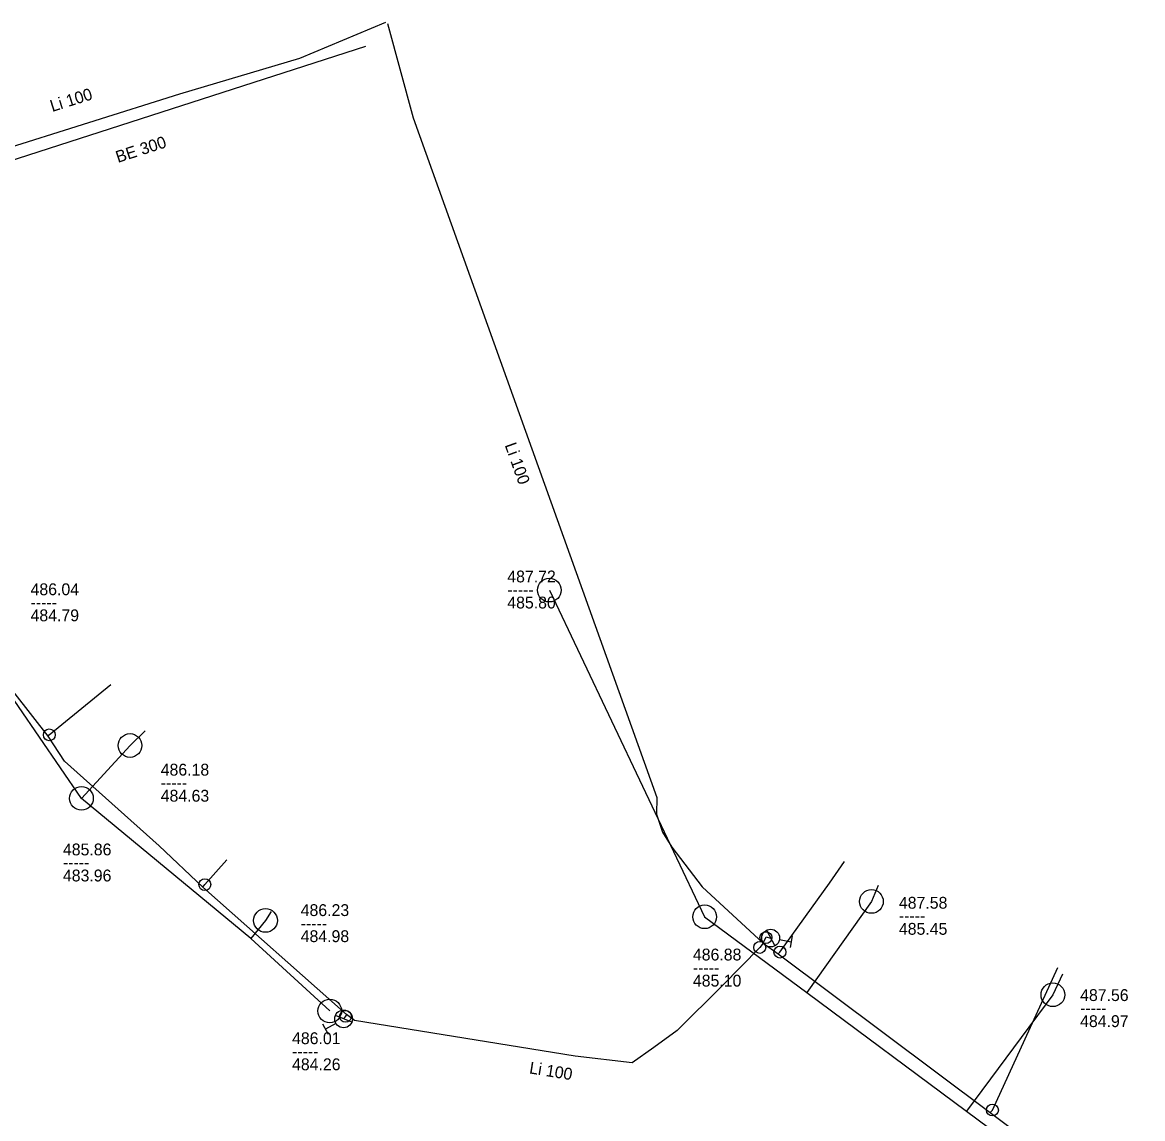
# Model space of a CAD drawing. Extents: x -685576 to -685145, y -1163436 to -1162895.
# Drawn here: x -685302.8 to -685208.3, y -1163269 to -1163176.5 of the extents above; entities that cross this region are included whole.
import ezdxf

# ---------------------------------------------------------------- set-up
doc = ezdxf.new("R2010")
doc.units = 0
doc.layers.add('Level 0', color=7, linetype='Continuous')

msp = doc.modelspace()

# ---------------------------------------------------------------- linework, layer by layer
at = {"layer": 'Level 0'}
for p, q in [((-685272.2, -1163176.49), (-685279.46, -1163179.53)), ((-685272.03, -1163176.58), (-685269.88, -1163184.54)), ((-685273.88, -1163178.51), (-685315.45, -1163191.93)), ((-685279.46, -1163179.53), (-685289.58, -1163182.54)), ((-685289.58, -1163182.54), (-685314.18, -1163190.28)), ((-685269.88, -1163184.54), (-685249.32, -1163241.89)), ((-685258.38, -1163224.39), (-685245.28, -1163251.95)), ((-685297.86, -1163241.96), (-685309.45, -1163225.05)), ((-685300.66, -1163236.72), (-685309.3, -1163225.68)), ((-685300.57, -1163236.6), (-685295.39, -1163232.34)), ((-685300.66, -1163236.72), (-685300.57, -1163236.6)), ((-685299.28, -1163238.81), (-685300.66, -1163236.72)), ((-685292.49, -1163236.25), (-685293.76, -1163237.5)), ((-685293.76, -1163237.5), (-685297.86, -1163241.96)), ((-685291.29, -1163245.96), (-685299.28, -1163238.81)), ((-685283.57, -1163253.78), (-685297.86, -1163241.96)), ((-685249.32, -1163241.89), (-685249.35, -1163243.29)), ((-685249.35, -1163243.29), (-685248.84, -1163244.81)), ((-685248.84, -1163244.81), (-685248.06, -1163246.08)), ((-685287.62, -1163249.46), (-685291.29, -1163245.96)), ((-685248.06, -1163246.08), (-685245.49, -1163249.43)), ((-685287.45, -1163249.24), (-685285.59, -1163247.15)), ((-685234.74, -1163249.11), (-685233.49, -1163247.28)), ((-685287.62, -1163249.46), (-685287.45, -1163249.24)), ((-685238.93, -1163254.93), (-685234.74, -1163249.11)), ((-685230.63, -1163249.31), (-685231.21, -1163250.66)), ((-685275.49, -1163260.19), (-685287.62, -1163249.46)), ((-685245.49, -1163249.43), (-685240.34, -1163254.18)), ((-685231.21, -1163250.66), (-685236.66, -1163258.35)), ((-685281.86, -1163251.51), (-685282.33, -1163252.26)), ((-685245.28, -1163251.95), (-685236.66, -1163258.35)), ((-685282.33, -1163252.26), (-685283.57, -1163253.78)), ((-685240.063, -1163253.091), (-685239.356, -1163254.414)), ((-685276.91, -1163259.9), (-685283.57, -1163253.78)), ((-685240.34, -1163254.18), (-685240.11, -1163253.71)), ((-685240.11, -1163253.71), (-685240.08, -1163253.63)), ((-685240.08, -1163253.63), (-685239.71, -1163253.75)), ((-685238.971, -1163253.88), (-685237.987, -1163254.054)), ((-685237.9, -1163253.561), (-685238.073, -1163254.546)), ((-685240.63, -1163254.54), (-685243.77, -1163257.74)), ((-685240.34, -1163254.18), (-685240.63, -1163254.54)), ((-685240.34, -1163254.18), (-685239.09, -1163255.09)), ((-685239.09, -1163255.09), (-685238.93, -1163254.93)), ((-685239.09, -1163255.09), (-685221.2, -1163268.46)), ((-685221, -1163268.26), (-685215.47, -1163256.23)), ((-685215.1, -1163256.8), (-685215.9, -1163258.53)), ((-685243.77, -1163257.74), (-685247.6, -1163261.56)), ((-685236.66, -1163258.35), (-685223.18, -1163268.34)), ((-685215.9, -1163258.53), (-685223.18, -1163268.34)), ((-685275.046, -1163260.848), (-685276.438, -1163260.289)), ((-685275.58, -1163260.35), (-685275.74, -1163260.57)), ((-685275.49, -1163260.19), (-685275.58, -1163260.35)), ((-685274.82, -1163260.69), (-685275.49, -1163260.19)), ((-685256.19, -1163263.72), (-685274.82, -1163260.69)), ((-685277.006, -1163261.878), (-685277.506, -1163261.012)), ((-685276.39, -1163260.945), (-685277.256, -1163261.445)), ((-685247.6, -1163261.56), (-685249.56, -1163262.98)), ((-685249.56, -1163262.98), (-685251.4, -1163264.27)), ((-685251.4, -1163264.27), (-685256.19, -1163263.72)), ((-685221.2, -1163268.46), (-685221, -1163268.26)), ((-685223.18, -1163268.34), (-685208.33, -1163279.35)), ((-685221.2, -1163268.46), (-685209.27, -1163277.38))]:
    msp.add_line(p, q, dxfattribs=at)
for centre, radius in [((-685258.38, -1163224.39), 1), ((-685300.57, -1163236.6), 0.5), ((-685293.76, -1163237.5), 1), ((-685297.86, -1163241.96), 1), ((-685287.45, -1163249.24), 0.5), ((-685231.21, -1163250.66), 1), ((-685282.33, -1163252.26), 1), ((-685245.28, -1163251.95), 1), ((-685239.71, -1163253.75), 0.75), ((-685240.63, -1163254.54), 0.5), ((-685240.11, -1163253.71), 0.5), ((-685238.93, -1163254.93), 0.5), ((-685215.9, -1163258.53), 1), ((-685276.91, -1163259.9), 1), ((-685275.74, -1163260.57), 0.75), ((-685275.58, -1163260.35), 0.5), ((-685221, -1163268.26), 0.5)]:
    msp.add_circle(centre, radius, dxfattribs=at)

# ---------------------------------------------------------------- texts
for s, rotation, p in [('Li 100', 17.465, (-685300.32, -1163184.05)), ('BE 300', 17.892, (-685294.78, -1163188.35)), ('Li 100', 289.723, (-685262.16, -1163212.15)), ('Li 100', 350.762, (-685260.12, -1163265.16))]:
    msp.add_text(s, height=1, rotation=rotation, dxfattribs=at).set_placement(p)
for s, p in [('487.72', (-685261.93, -1163223.74)), ('486.04', (-685302.15, -1163224.82)), ('-----', (-685261.93, -1163224.84)), ('-----', (-685302.15, -1163225.92)), ('485.80', (-685261.93, -1163225.94)), ('484.79', (-685302.15, -1163227.02)), ('486.18', (-685291.17, -1163240.04)), ('-----', (-685291.17, -1163241.14)), ('484.63', (-685291.17, -1163242.24)), ('485.86', (-685299.42, -1163246.77)), ('-----', (-685299.42, -1163247.87)), ('483.96', (-685299.42, -1163248.97)), ('487.58', (-685228.89, -1163251.27)), ('486.23', (-685279.36, -1163251.89)), ('-----', (-685228.89, -1163252.37)), ('484.98', (-685279.36, -1163254.09)), ('-----', (-685279.36, -1163252.99)), ('485.45', (-685228.89, -1163253.47)), ('486.88', (-685246.27, -1163255.64)), ('485.10', (-685246.27, -1163257.84)), ('-----', (-685246.27, -1163256.74)), ('487.56', (-685213.6, -1163259.06)), ('-----', (-685213.6, -1163260.16)), ('484.97', (-685213.6, -1163261.26)), ('486.01', (-685280.09, -1163262.7)), ('-----', (-685280.09, -1163263.8)), ('484.26', (-685280.09, -1163264.9))]:
    msp.add_text(s, height=1, dxfattribs=at).set_placement(p)

doc.saveas('drawing.dxf')
